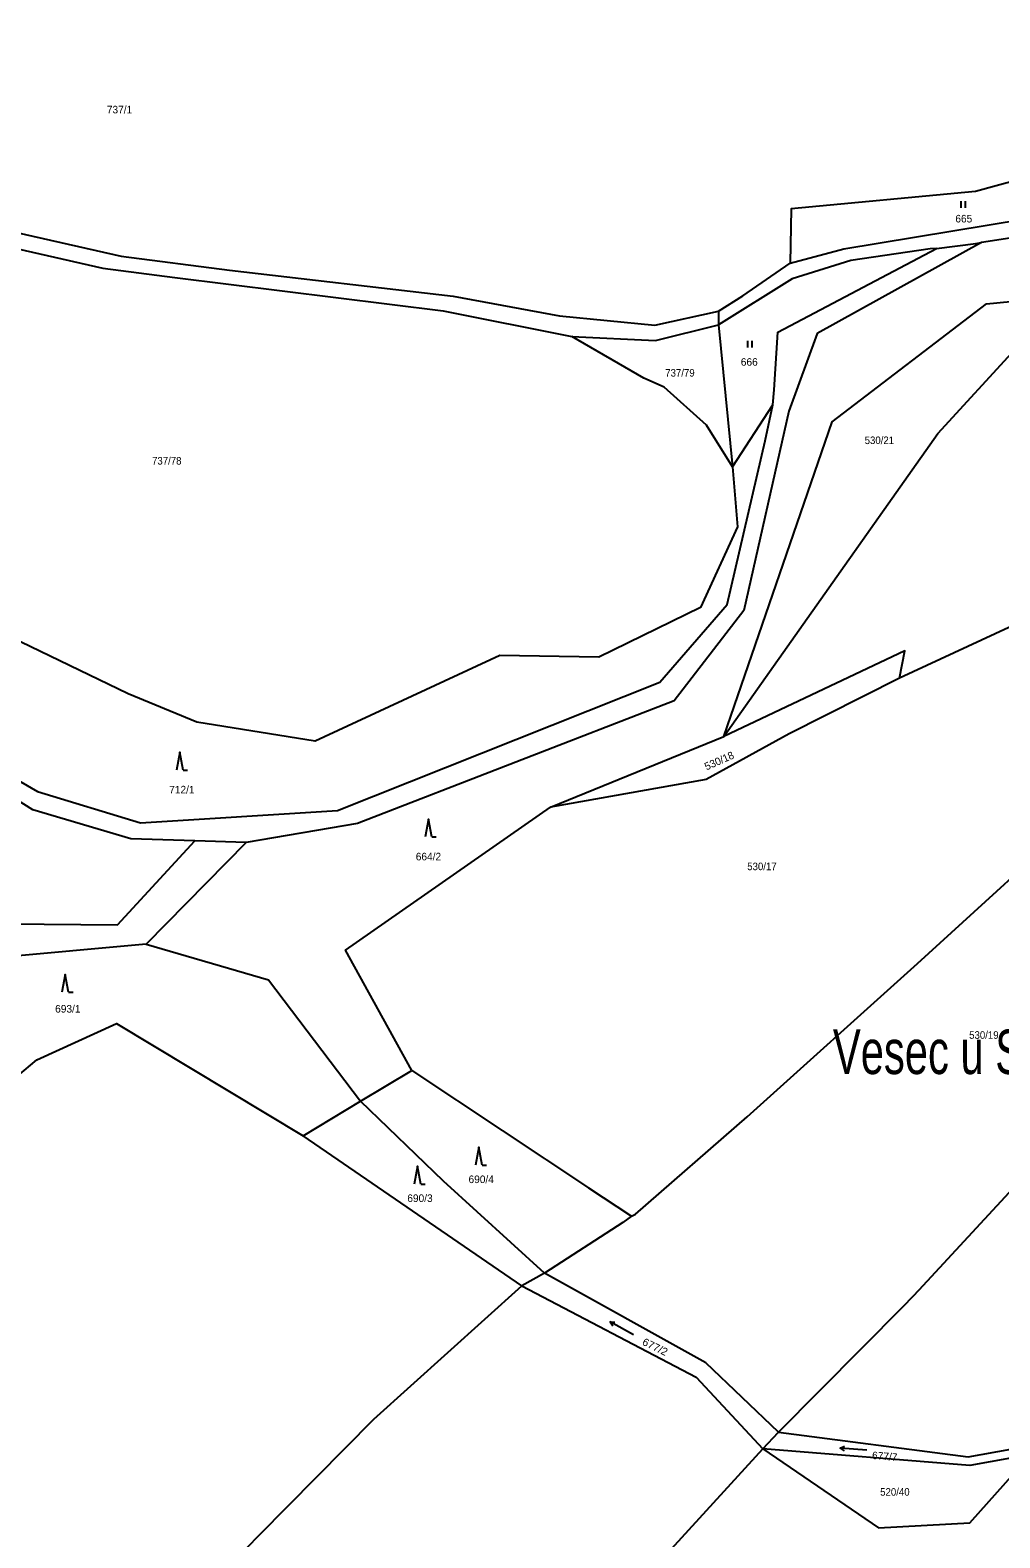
# Model space of a CAD drawing. Extents: x -687135 to -684370, y -1007309 to -1005782.
# Drawn here: x -685826.9 to -685609.3, y -1006924.3 to -1006586 of the extents above; entities that cross this region are included whole.
import ezdxf
from ezdxf.enums import TextEntityAlignment as Align

# ---------------------------------------------------------------- set-up
doc = ezdxf.new("R2010")
doc.units = 0
doc.header["$LTSCALE"] = 0.68
for name, color, linetype, lineweight in [('1', 7, 'Continuous', 25), ('3', 7, 'Continuous', 25), ('7', 7, 'Continuous', 13)]:
    doc.layers.add(name, color=color, linetype=linetype, lineweight=lineweight)
doc.layers.add('2', color=7, linetype='Continuous')

msp = doc.modelspace()

# ---------------------------------------------------------------- linework, layer by layer
at = {"layer": '1'}
for p, q in [((-685672.41, -1006649.09), (-685672.37, -1006652.11)), ((-685778.39, -1006768.31), (-685789.93, -1006767.93)), ((-685778.39, -1006768.31), (-685800.81, -1006791.11)), ((-685800.81, -1006791.11), (-685841.9, -1006794.86)), ((-685662.46, -1006904.3), (-685658.94, -1006900.62)), ((-685697.79, -1006943.02), (-685662.46, -1006904.3))]:
    msp.add_line(p, q, dxfattribs=at)
for points in [[(-686019.08, -1006554.64), (-685953.3, -1006588.31), (-685908.41, -1006602.66), (-685899.85, -1006607.32), (-685862.63, -1006623.68), (-685839.89, -1006629.21), (-685806.41, -1006636.76), (-685782.11, -1006639.91), (-685731.95, -1006645.69), (-685708.06, -1006650.1), (-685686.69, -1006652.24), (-685672.41, -1006649.09)], [(-685902.96, -1006609.62), (-685863.86, -1006627.32), (-685810.59, -1006639.46), (-685794.4, -1006641.53), (-685734.22, -1006648.98), (-685705.31, -1006654.75)], [(-685575.17, -1006611.42), (-685614.74, -1006622.25), (-685656.12, -1006626.09), (-685656.29, -1006638.32)], [(-685656.29, -1006638.32), (-685644.27, -1006635.08), (-685603.94, -1006628.44), (-685572.86, -1006633.51), (-685575.17, -1006611.42)], [(-685557.54, -1006649.32), (-685581.72, -1006636.09), (-685603.1, -1006632.14), (-685613.39, -1006633.71)], [(-685613.39, -1006633.71), (-685650.29, -1006654.07), (-685656.63, -1006671.55), (-685666.74, -1006716.27), (-685682.33, -1006736.49), (-685753.38, -1006764.03), (-685778.39, -1006768.31)], [(-685623.51, -1006635.02), (-685624.92, -1006635.11), (-685642.72, -1006637.74), (-685655.87, -1006641.85), (-685672.37, -1006652.11), (-685669.25, -1006683.97), (-685660.21, -1006670.08)], [(-685660.21, -1006670.08), (-685659.93, -1006666.71), (-685659.1, -1006653.78), (-685623.51, -1006635.02)], [(-685623.51, -1006635.02), (-685614.63, -1006633.9), (-685613.39, -1006633.71)], [(-685672.41, -1006649.09), (-685666.94, -1006645.65), (-685656.29, -1006638.32)], [(-685671.21, -1006744.5), (-685646.88, -1006673.94), (-685612.23, -1006647.46), (-685588.5, -1006645.15), (-685557.54, -1006649.32)], [(-685705.31, -1006654.75), (-685686.56, -1006655.63), (-685672.37, -1006652.11)], [(-685671.21, -1006744.5), (-685623.21, -1006676.54), (-685605.72, -1006657.51), (-685583.18, -1006651.43), (-685558.38, -1006660.99)], [(-685669.25, -1006683.97), (-685675.07, -1006674.65), (-685684.59, -1006666.16), (-685689.14, -1006664.09), (-685705.31, -1006654.75)], [(-685876.62, -1006730.81), (-685840.65, -1006747.95), (-685825.24, -1006756.86), (-685802.11, -1006763.88), (-685757.92, -1006761.14), (-685685.53, -1006732.35), (-685670.46, -1006714.87), (-685661.89, -1006678.2), (-685660.21, -1006670.08)], [(-685669.25, -1006683.97), (-685668.16, -1006697.46), (-685676.45, -1006715.56), (-685699.23, -1006726.7), (-685721.43, -1006726.36), (-685762.88, -1006745.55), (-685789.43, -1006741.26), (-685804.85, -1006734.92), (-685844.42, -1006715.9), (-685866.37, -1006705.16)], [(-685569.03, -1006709.19), (-685598.05, -1006715.78), (-685631.8, -1006731.45)], [(-685631.8, -1006731.45), (-685630.57, -1006725.29), (-685671.21, -1006744.5)], [(-685691.91, -1006852.16), (-685690.99, -1006851.65), (-685665.96, -1006829.87), (-685627.75, -1006795.4), (-685587.91, -1006759.11), (-685564.69, -1006738.38), (-685556.79, -1006728.34)], [(-685631.8, -1006731.45), (-685656.53, -1006743.94), (-685675.18, -1006754.13), (-685710.07, -1006760.34)], [(-685789.93, -1006767.93), (-685804.25, -1006767.45), (-685826.27, -1006760.94), (-685841.68, -1006751.35), (-685862.91, -1006740.67)], [(-685741.24, -1006819.46), (-685756.07, -1006792.47), (-685710.07, -1006760.34), (-685671.21, -1006744.5)], [(-686343.59, -1006806.28), (-686314.7, -1006796.2), (-686276.55, -1006786.38), (-686120.2, -1006767.85), (-686044, -1006772.76), (-685931.45, -1006773.3), (-685897.9, -1006785.97), (-685807.25, -1006786.78), (-685789.93, -1006767.93)], [(-685658.94, -1006900.62), (-685630.94, -1006872.36), (-685628.68, -1006870.1), (-685627.38, -1006868.69), (-685595.17, -1006833.9), (-685542.53, -1006783.15)], [(-685800.81, -1006791.11), (-685773.4, -1006799.11), (-685752.72, -1006826.35), (-685741.24, -1006819.46)], [(-685836.8, -1006826.62), (-685825.36, -1006817.08), (-685807.49, -1006808.9), (-685765.63, -1006834.08), (-685752.72, -1006826.35)], [(-685741.24, -1006819.46), (-685720.98, -1006832.89), (-685701.55, -1006845.77), (-685691.91, -1006852.16)], [(-685711.45, -1006864.94), (-685734.13, -1006844.27), (-685752.72, -1006826.35)], [(-685839.55, -1006989.44), (-685809.54, -1006958.71), (-685775.47, -1006923.66), (-685749.74, -1006897.67), (-685716.52, -1006867.72), (-685765.63, -1006834.08)], [(-685691.91, -1006852.16), (-685693.88, -1006853.58), (-685711.45, -1006864.94)], [(-685658.94, -1006900.62), (-685675.22, -1006885.01), (-685711.45, -1006864.94), (-685716.52, -1006867.72)], [(-685716.52, -1006867.72), (-685677.4, -1006888.26), (-685662.46, -1006904.3)], [(-685658.94, -1006900.62), (-685616.35, -1006906.11), (-685600.16, -1006903.18), (-685575.05, -1006875.09)], [(-685602.32, -1006905.6), (-685615.99, -1006908.08), (-685662.46, -1006904.3)], [(-685662.46, -1006904.3), (-685636.48, -1006922.07), (-685616.01, -1006920.93), (-685602.32, -1006905.6)]]:
    msp.add_lwpolyline(points, dxfattribs=at)
at = {"layer": '3'}
for p, q in [((-685617.941, -1006625.9), (-685617.941, -1006624.4)), ((-685616.94, -1006625.9), (-685616.94, -1006624.4)), ((-685665.841, -1006657.22), (-685665.841, -1006655.72)), ((-685664.84, -1006657.22), (-685664.84, -1006655.72)), ((-685792.54, -1006752.04), (-685791.544, -1006752.04)), ((-685736.73, -1006767.05), (-685735.734, -1006767.05)), ((-685818.23, -1006801.89), (-685817.234, -1006801.89)), ((-685725.42, -1006840.66), (-685724.424, -1006840.66)), ((-685739.22, -1006844.91), (-685738.224, -1006844.91)), ((-685696.735, -1006875.84), (-685695.637, -1006875.875)), ((-685645.129, -1006904.191), (-685644.119, -1006903.759))]:
    msp.add_line(p, q, dxfattribs=at)
for points in [[(-685792.54, -1006752.04), (-685793.29, -1006748.04), (-685794.04, -1006752.04)], [(-685736.73, -1006767.05), (-685737.48, -1006763.05), (-685738.23, -1006767.05)], [(-685818.23, -1006801.89), (-685818.98, -1006797.89), (-685819.73, -1006801.89)], [(-685725.42, -1006840.66), (-685726.17, -1006836.66), (-685726.92, -1006840.66)], [(-685739.22, -1006844.91), (-685739.97, -1006840.91), (-685740.72, -1006844.91)], [(-685691.487, -1006878.749), (-685696.735, -1006875.84), (-685696.123, -1006876.752)], [(-685639.144, -1006904.61), (-685645.129, -1006904.191), (-685644.189, -1006904.759)]]:
    msp.add_lwpolyline(points, dxfattribs=at)

# ---------------------------------------------------------------- texts
at = {"layer": '2'}
for s, p in [('737/1', (-685809.65, -1006604.71)), ('665', (-685619.25, -1006629.179)), ('666', (-685667.39, -1006661.32)), ('712/1', (-685795.66, -1006757.28)), ('664/2', (-685740.33, -1006772.299)), ('693/1', (-685821.25, -1006806.45)), ('690/4', (-685728.49, -1006844.7)), ('690/3', (-685742.23, -1006848.94))]:
    msp.add_text(s, height=1.7, dxfattribs=at).set_placement(p)
at = {"layer": '2', "width": 0.95}
for s, p in [('737/79', (-685684.35, -1006663.76)), ('530/21', (-685639.6, -1006678.9)), ('737/78', (-685799.51, -1006683.5)), ('530/17', (-685665.95, -1006774.5)), ('530/19', (-685616.15, -1006812.33)), ('520/40', (-685636.12, -1006914.84))]:
    msp.add_text(s, height=1.7, dxfattribs=at).set_placement(p)
at = {"layer": '2'}
for s, rotation, p in [('530/18', 24, (-685675.074, -1006752.136)), ('677/7', 355, (-685638.004, -1006906.596))]:
    msp.add_text(s, height=1.7, rotation=rotation, dxfattribs=at).set_placement(p)
at = {"layer": '2', "width": 1.05}
msp.add_text('677/2', height=1.7, rotation=334, dxfattribs=at).set_placement((-685689.682, -1006880.903))
at = {"layer": '7', "width": 0.7}
msp.add_text('Vesec u Sobotky 683361', height=10, dxfattribs=at).set_placement((-685594.68, -1006820.237), align=Align.CENTER)

doc.saveas('drawing.dxf')
